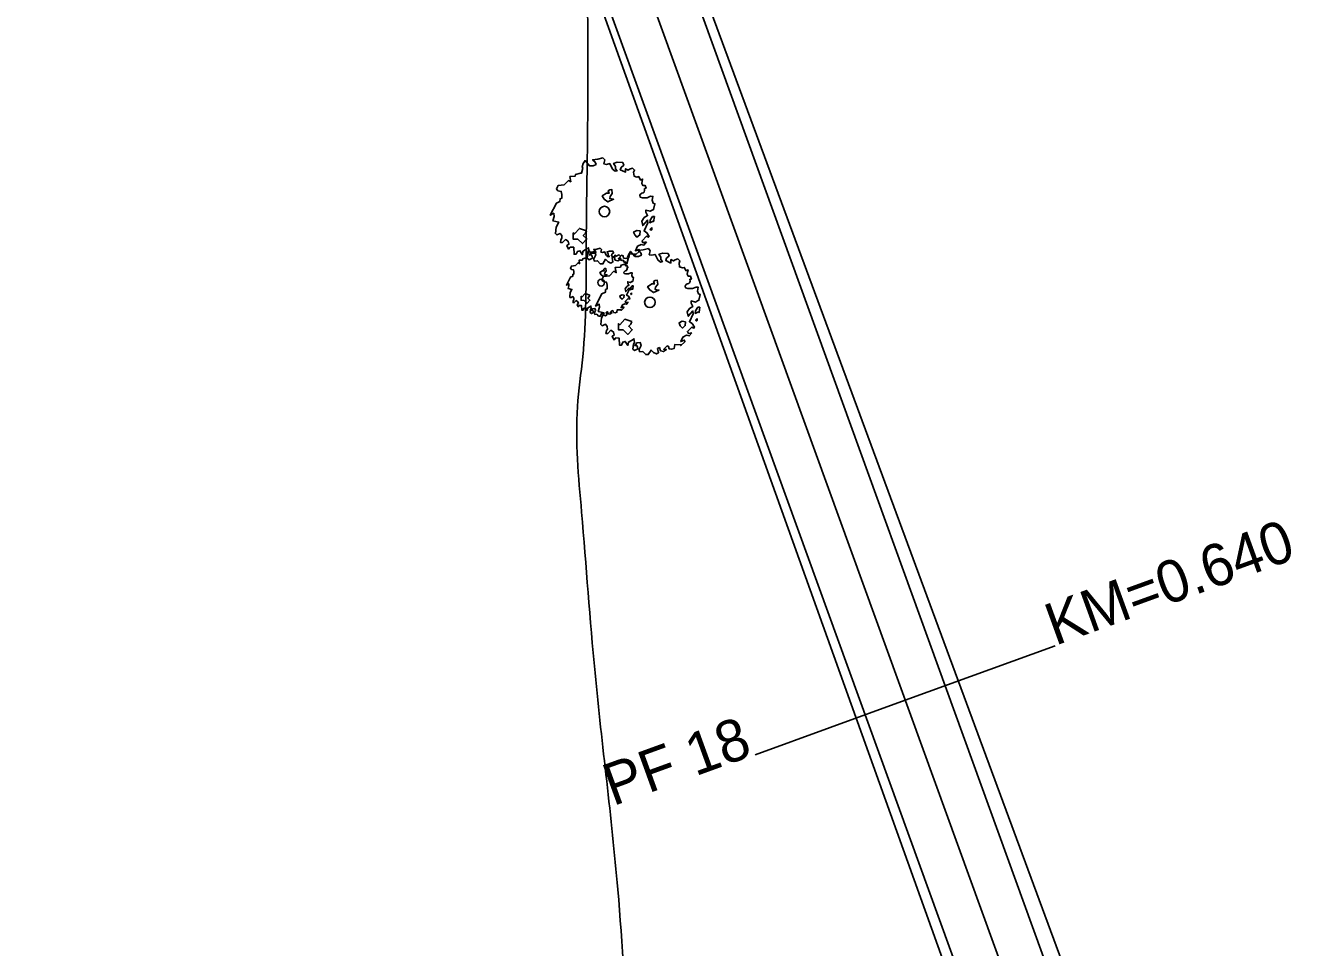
# Model space of a CAD drawing. Extents: x -475575 to -473225, y -1116053 to -1114104.
# Drawn here: x -474299.4 to -474238.8, y -1114903.1 to -1114859.8 of the extents above; entities that cross this region are included whole.
import ezdxf

# ---------------------------------------------------------------- set-up
doc = ezdxf.new("R2010")
doc.units = 0
for name, color, linetype in [('CESTN___P____KOP_N__VRH__Construction_', 7, 'Continuous'), ('IP', 7, 'Continuous'), ('POLYGONY_SITUACE_PF', 7, 'Continuous'), ('POLYGONY_SITUACE_PF_POPISY', 7, 'Continuous'), ('POLYGONY_SITUACE_PO', 7, 'Continuous'), ('Vrstevnice_vedlejsi', 7, 'Continuous')]:
    doc.layers.add(name, color=color, linetype=linetype)

msp = doc.modelspace()

# ---------------------------------------------------------------- linework, layer by layer
at = {"layer": 'CESTN___P____KOP_N__VRH__Construction_'}
for p, q in [((-474274.588, -1114840.004), (-474244.59, -1114922.733)), ((-474243.773, -1114922.437), (-474274.295, -1114839.898)), ((-474278.604, -1114841.46), (-474248.886, -1114924.291))]:
    msp.add_line(p, q, dxfattribs=at)
msp.add_lwpolyline([(-474278.348, -1114841.367), (-474248.351, -1114924.097)], dxfattribs=at)
at = {"layer": 'IP'}
for points in [[(-474270.23, -1114869.921), (-474270.344, -1114870.07), (-474270.473, -1114870.036), (-474270.649, -1114870.127), (-474270.745, -1114870.336), (-474270.574, -1114870.27), (-474270.55, -1114870.348), (-474270.744, -1114870.528), (-474270.732, -1114870.493), (-474271.028, -1114870.479), (-474271.049, -1114870.66), (-474271.178, -1114870.7), (-474271.296, -1114870.677), (-474271.321, -1114870.573), (-474271.391, -1114870.544), (-474271.544, -1114870.695), (-474271.42, -1114870.716), (-474271.563, -1114870.809), (-474271.697, -1114870.772), (-474271.747, -1114870.619), (-474271.841, -1114870.666), (-474271.799, -1114870.859), (-474271.893, -1114870.914), (-474272.029, -1114870.855), (-474272.142, -1114870.737), (-474272.271, -1114870.95), (-474272.393, -1114870.946), (-474272.523, -1114870.803), (-474272.678, -1114870.818), (-474272.702, -1114870.71), (-474272.61, -1114870.52), (-474272.659, -1114870.375), (-474272.818, -1114870.4), (-474272.902, -1114870.536), (-474272.818, -1114870.525), (-474272.781, -1114870.593), (-474272.762, -1114870.683), (-474272.915, -1114870.756), (-474273.004, -1114870.691), (-474272.974, -1114870.466), (-474272.924, -1114870.388), (-474272.951, -1114870.196), (-474272.959, -1114870.217), (-474273.207, -1114870.357), (-474273.229, -1114870.521), (-474273.351, -1114870.332), (-474273.472, -1114870.37), (-474273.528, -1114870.503), (-474273.626, -1114870.5), (-474273.643, -1114870.174), (-474273.802, -1114870.168), (-474273.88, -1114870.258), (-474273.973, -1114870.095), (-474273.872, -1114870.027), (-474273.904, -1114869.89), (-474274.028, -1114869.808), (-474274.175, -1114869.951), (-474274.263, -1114869.952), (-474274.242, -1114869.817), (-474274.196, -1114869.747), (-474274.202, -1114869.625), (-474274.285, -1114869.518), (-474274.443, -1114869.595), (-474274.504, -1114869.53), (-474274.471, -1114869.22), (-474274.349, -1114868.99), (-474274.619, -1114868.931), (-474274.564, -1114868.723), (-474274.581, -1114868.576), (-474274.749, -1114868.669), (-474274.45, -1114868.092), (-474274.288, -1114868.023), (-474274.282, -1114867.894), (-474274.207, -1114867.866), (-474274.203, -1114867.685), (-474274.23, -1114867.548), (-474274.387, -1114867.519), (-474274.457, -1114867.432), (-474274.377, -1114867.276), (-474274.093, -1114867.244), (-474273.891, -1114867.036), (-474273.78, -1114867.096), (-474273.824, -1114866.852), (-474273.579, -1114866.836), (-474273.552, -1114866.747), (-474273.328, -1114866.684), (-474273.275, -1114866.684), (-474273.212, -1114866.454), (-474273.251, -1114866.387), (-474273.192, -1114866.229), (-474273.112, -1114866.103), (-474272.902, -1114866.339), (-474272.735, -1114866.345), (-474272.592, -1114866.277), (-474272.627, -1114866.169), (-474272.755, -1114866.062), (-474272.516, -1114866.031), (-474272.27, -1114865.972), (-474272.183, -1114866.068), (-474272.224, -1114866.257), (-474272.1, -1114866.276), (-474271.949, -1114866.244), (-474271.816, -1114866.502), (-474271.702, -1114866.6), (-474271.607, -1114866.582), (-474271.684, -1114866.485), (-474271.684, -1114866.37), (-474271.769, -1114866.235), (-474271.594, -1114866.181), (-474271.341, -1114866.196), (-474271.293, -1114866.316), (-474271.414, -1114866.419), (-474271.454, -1114866.528), (-474271.243, -1114866.63), (-474271.208, -1114866.64), (-474271.205, -1114866.486), (-474271.087, -1114866.544), (-474271.014, -1114866.499), (-474270.884, -1114866.456), (-474270.782, -1114866.546), (-474270.826, -1114866.649), (-474270.809, -1114866.828), (-474270.67, -1114866.873), (-474270.585, -1114866.854), (-474270.497, -1114867.013), (-474270.403, -1114866.972), (-474270.446, -1114867.177), (-474270.395, -1114867.268), (-474270.29, -1114867.264), (-474270.245, -1114867.399), (-474270.315, -1114867.412), (-474270.309, -1114867.494), (-474270.335, -1114867.582), (-474270.373, -1114867.616), (-474270.44, -1114867.631), (-474270.5, -1114867.673), (-474270.541, -1114867.727), (-474270.517, -1114867.811), (-474270.418, -1114867.847), (-474270.197, -1114867.848), (-474270.027, -1114867.774), (-474269.923, -1114867.783), (-474269.953, -1114867.965), (-474269.909, -1114868.095), (-474269.83, -1114868.127), (-474269.892, -1114868.399), (-474269.96, -1114868.421), (-474270.055, -1114868.483), (-474270.252, -1114868.428), (-474270.26, -1114868.527), (-474270.172, -1114868.683), (-474270.33, -1114868.78), (-474270.44, -1114868.946), (-474270.397, -1114869.149), (-474270.174, -1114868.894), (-474270.162, -1114869.03), (-474270.339, -1114869.407), (-474270.204, -1114869.489), (-474270.104, -1114869.658), (-474270.125, -1114869.703), (-474270.228, -1114869.655), (-474270.432, -1114869.863), (-474270.388, -1114869.959)], [(-474271.959, -1114867.63), (-474272.102, -1114867.63), (-474272.304, -1114867.758), (-474272.207, -1114867.91), (-474272.032, -1114868.037), (-474271.772, -1114867.915), (-474271.948, -1114867.884), (-474271.93, -1114867.782), (-474271.86, -1114867.686), (-474271.83, -1114867.644), (-474271.853, -1114867.456), (-474271.947, -1114867.468), (-474272.023, -1114867.518), (-474271.993, -1114867.591)], [(-474269.939, -1114868.723), (-474270.052, -1114868.901), (-474270.066, -1114869.016), (-474269.912, -1114868.942), (-474269.888, -1114868.974), (-474269.853, -1114868.726)], [(-474273.043, -1114869.398), (-474273.371, -1114869.284), (-474273.612, -1114869.545), (-474273.665, -1114869.496), (-474273.672, -1114869.786), (-474273.452, -1114869.791), (-474273.23, -1114870), (-474273.022, -1114869.778), (-474273.191, -1114869.619), (-474273.093, -1114869.515)], [(-474270.519, -1114869.405), (-474270.676, -1114869.378), (-474270.826, -1114869.455), (-474270.774, -1114869.594), (-474270.67, -1114869.703), (-474270.533, -1114869.59)], [(-474269.973, -1114869.248), (-474270.051, -1114869.324), (-474270.014, -1114869.372), (-474269.979, -1114869.348)], [(-474271.088, -1114872.749), (-474271.161, -1114872.845), (-474271.244, -1114872.823), (-474271.356, -1114872.881), (-474271.418, -1114873.016), (-474271.308, -1114872.973), (-474271.293, -1114873.023), (-474271.417, -1114873.138), (-474271.41, -1114873.116), (-474271.599, -1114873.107), (-474271.613, -1114873.224), (-474271.695, -1114873.249), (-474271.771, -1114873.234), (-474271.787, -1114873.167), (-474271.832, -1114873.149), (-474271.93, -1114873.246), (-474271.851, -1114873.259), (-474271.942, -1114873.319), (-474272.028, -1114873.295), (-474272.061, -1114873.197), (-474272.121, -1114873.227), (-474272.094, -1114873.351), (-474272.154, -1114873.386), (-474272.241, -1114873.348), (-474272.314, -1114873.273), (-474272.397, -1114873.409), (-474272.475, -1114873.406), (-474272.558, -1114873.315), (-474272.657, -1114873.325), (-474272.673, -1114873.255), (-474272.614, -1114873.133), (-474272.645, -1114873.04), (-474272.747, -1114873.057), (-474272.801, -1114873.144), (-474272.747, -1114873.137), (-474272.723, -1114873.18), (-474272.712, -1114873.238), (-474272.81, -1114873.285), (-474272.867, -1114873.243), (-474272.847, -1114873.098), (-474272.815, -1114873.049), (-474272.832, -1114872.926), (-474272.838, -1114872.939), (-474272.997, -1114873.029), (-474273.011, -1114873.134), (-474273.089, -1114873.013), (-474273.167, -1114873.037), (-474273.203, -1114873.123), (-474273.266, -1114873.121), (-474273.276, -1114872.912), (-474273.379, -1114872.907), (-474273.428, -1114872.965), (-474273.488, -1114872.861), (-474273.424, -1114872.817), (-474273.444, -1114872.729), (-474273.523, -1114872.677), (-474273.618, -1114872.768), (-474273.674, -1114872.769), (-474273.661, -1114872.682), (-474273.631, -1114872.637), (-474273.635, -1114872.56), (-474273.688, -1114872.491), (-474273.79, -1114872.54), (-474273.829, -1114872.498), (-474273.807, -1114872.299), (-474273.729, -1114872.152), (-474273.903, -1114872.114), (-474273.867, -1114871.981), (-474273.878, -1114871.887), (-474273.986, -1114871.946), (-474273.794, -1114871.576), (-474273.69, -1114871.532), (-474273.686, -1114871.449), (-474273.638, -1114871.431), (-474273.636, -1114871.315), (-474273.653, -1114871.227), (-474273.754, -1114871.209), (-474273.798, -1114871.153), (-474273.747, -1114871.053), (-474273.565, -1114871.033), (-474273.436, -1114870.899), (-474273.364, -1114870.938), (-474273.393, -1114870.781), (-474273.236, -1114870.77), (-474273.218, -1114870.713), (-474273.074, -1114870.673), (-474273.04, -1114870.673), (-474273, -1114870.525), (-474273.025, -1114870.483), (-474272.987, -1114870.381), (-474272.936, -1114870.3), (-474272.801, -1114870.452), (-474272.694, -1114870.456), (-474272.603, -1114870.412), (-474272.625, -1114870.343), (-474272.707, -1114870.274), (-474272.554, -1114870.254), (-474272.396, -1114870.216), (-474272.34, -1114870.278), (-474272.366, -1114870.4), (-474272.287, -1114870.412), (-474272.19, -1114870.391), (-474272.105, -1114870.556), (-474272.031, -1114870.619), (-474271.971, -1114870.608), (-474272.02, -1114870.545), (-474272.02, -1114870.472), (-474272.074, -1114870.385), (-474271.962, -1114870.351), (-474271.8, -1114870.36), (-474271.769, -1114870.437), (-474271.847, -1114870.503), (-474271.872, -1114870.573), (-474271.737, -1114870.639), (-474271.714, -1114870.645), (-474271.713, -1114870.546), (-474271.637, -1114870.583), (-474271.59, -1114870.555), (-474271.507, -1114870.527), (-474271.441, -1114870.585), (-474271.47, -1114870.651), (-474271.459, -1114870.765), (-474271.37, -1114870.794), (-474271.315, -1114870.782), (-474271.259, -1114870.884), (-474271.199, -1114870.858), (-474271.226, -1114870.989), (-474271.193, -1114871.048), (-474271.126, -1114871.045), (-474271.097, -1114871.132), (-474271.142, -1114871.14), (-474271.138, -1114871.193), (-474271.155, -1114871.249), (-474271.18, -1114871.271), (-474271.222, -1114871.28), (-474271.261, -1114871.308), (-474271.287, -1114871.342), (-474271.272, -1114871.396), (-474271.208, -1114871.419), (-474271.066, -1114871.42), (-474270.957, -1114871.372), (-474270.89, -1114871.378), (-474270.91, -1114871.495), (-474270.881, -1114871.578), (-474270.831, -1114871.598), (-474270.871, -1114871.773), (-474270.914, -1114871.787), (-474270.975, -1114871.827), (-474271.102, -1114871.792), (-474271.107, -1114871.855), (-474271.051, -1114871.955), (-474271.152, -1114872.018), (-474271.222, -1114872.124), (-474271.195, -1114872.254), (-474271.052, -1114872.091), (-474271.044, -1114872.178), (-474271.158, -1114872.419), (-474271.071, -1114872.472), (-474271.007, -1114872.58), (-474271.02, -1114872.609), (-474271.086, -1114872.578), (-474271.217, -1114872.712), (-474271.189, -1114872.773)], [(-474268.097, -1114874.186), (-474268.211, -1114874.335), (-474268.34, -1114874.301), (-474268.516, -1114874.392), (-474268.611, -1114874.601), (-474268.44, -1114874.535), (-474268.417, -1114874.613), (-474268.61, -1114874.792), (-474268.599, -1114874.757), (-474268.894, -1114874.743), (-474268.915, -1114874.925), (-474269.044, -1114874.964), (-474269.162, -1114874.942), (-474269.187, -1114874.837), (-474269.258, -1114874.808), (-474269.411, -1114874.959), (-474269.287, -1114874.981), (-474269.429, -1114875.074), (-474269.563, -1114875.037), (-474269.614, -1114874.884), (-474269.708, -1114874.931), (-474269.666, -1114875.124), (-474269.759, -1114875.178), (-474269.895, -1114875.12), (-474270.009, -1114875.002), (-474270.137, -1114875.215), (-474270.26, -1114875.21), (-474270.389, -1114875.068), (-474270.544, -1114875.083), (-474270.568, -1114874.975), (-474270.477, -1114874.784), (-474270.525, -1114874.64), (-474270.684, -1114874.665), (-474270.768, -1114874.801), (-474270.684, -1114874.79), (-474270.647, -1114874.858), (-474270.629, -1114874.948), (-474270.782, -1114875.02), (-474270.871, -1114874.955), (-474270.84, -1114874.73), (-474270.79, -1114874.652), (-474270.817, -1114874.461), (-474270.825, -1114874.481), (-474271.074, -1114874.622), (-474271.095, -1114874.785), (-474271.218, -1114874.597), (-474271.339, -1114874.634), (-474271.395, -1114874.768), (-474271.492, -1114874.765), (-474271.509, -1114874.439), (-474271.668, -1114874.432), (-474271.746, -1114874.523), (-474271.839, -1114874.36), (-474271.739, -1114874.291), (-474271.77, -1114874.154), (-474271.894, -1114874.073), (-474272.042, -1114874.215), (-474272.129, -1114874.216), (-474272.109, -1114874.081), (-474272.062, -1114874.011), (-474272.068, -1114873.89), (-474272.151, -1114873.783), (-474272.31, -1114873.86), (-474272.37, -1114873.794), (-474272.337, -1114873.484), (-474272.215, -1114873.255), (-474272.486, -1114873.195), (-474272.431, -1114872.987), (-474272.447, -1114872.841), (-474272.616, -1114872.934), (-474272.316, -1114872.357), (-474272.154, -1114872.288), (-474272.148, -1114872.158), (-474272.073, -1114872.131), (-474272.07, -1114871.95), (-474272.097, -1114871.813), (-474272.253, -1114871.784), (-474272.323, -1114871.697), (-474272.243, -1114871.541), (-474271.96, -1114871.509), (-474271.758, -1114871.301), (-474271.646, -1114871.361), (-474271.691, -1114871.117), (-474271.446, -1114871.1), (-474271.419, -1114871.012), (-474271.194, -1114870.948), (-474271.141, -1114870.949), (-474271.079, -1114870.718), (-474271.117, -1114870.652), (-474271.058, -1114870.494), (-474270.978, -1114870.368), (-474270.768, -1114870.604), (-474270.601, -1114870.61), (-474270.459, -1114870.542), (-474270.494, -1114870.433), (-474270.621, -1114870.326), (-474270.383, -1114870.296), (-474270.136, -1114870.236), (-474270.049, -1114870.333), (-474270.09, -1114870.522), (-474269.966, -1114870.541), (-474269.815, -1114870.509), (-474269.682, -1114870.767), (-474269.568, -1114870.865), (-474269.474, -1114870.847), (-474269.551, -1114870.749), (-474269.551, -1114870.635), (-474269.635, -1114870.5), (-474269.461, -1114870.446), (-474269.208, -1114870.461), (-474269.159, -1114870.581), (-474269.28, -1114870.684), (-474269.32, -1114870.793), (-474269.109, -1114870.895), (-474269.074, -1114870.905), (-474269.072, -1114870.75), (-474268.954, -1114870.809), (-474268.881, -1114870.764), (-474268.75, -1114870.721), (-474268.648, -1114870.811), (-474268.692, -1114870.914), (-474268.675, -1114871.092), (-474268.537, -1114871.137), (-474268.451, -1114871.119), (-474268.363, -1114871.277), (-474268.27, -1114871.236), (-474268.313, -1114871.441), (-474268.261, -1114871.533), (-474268.157, -1114871.528), (-474268.112, -1114871.663), (-474268.182, -1114871.677), (-474268.175, -1114871.759), (-474268.201, -1114871.846), (-474268.24, -1114871.881), (-474268.306, -1114871.895), (-474268.366, -1114871.938), (-474268.408, -1114871.992), (-474268.384, -1114872.075), (-474268.284, -1114872.112), (-474268.064, -1114872.112), (-474267.893, -1114872.039), (-474267.789, -1114872.048), (-474267.82, -1114872.23), (-474267.775, -1114872.36), (-474267.697, -1114872.391), (-474267.758, -1114872.664), (-474267.826, -1114872.686), (-474267.921, -1114872.748), (-474268.119, -1114872.693), (-474268.126, -1114872.791), (-474268.039, -1114872.947), (-474268.197, -1114873.045), (-474268.307, -1114873.211), (-474268.264, -1114873.413), (-474268.041, -1114873.159), (-474268.029, -1114873.294), (-474268.206, -1114873.672), (-474268.071, -1114873.754), (-474267.971, -1114873.922), (-474267.991, -1114873.968), (-474268.094, -1114873.919), (-474268.298, -1114874.127), (-474268.255, -1114874.223)], [(-474272.197, -1114871.28), (-474272.288, -1114871.28), (-474272.418, -1114871.362), (-474272.356, -1114871.459), (-474272.243, -1114871.541), (-474272.077, -1114871.463), (-474272.189, -1114871.443), (-474272.178, -1114871.377), (-474272.133, -1114871.316), (-474272.114, -1114871.289), (-474272.128, -1114871.169), (-474272.189, -1114871.176), (-474272.237, -1114871.208), (-474272.218, -1114871.255)], [(-474270.901, -1114871.981), (-474270.973, -1114872.095), (-474270.983, -1114872.169), (-474270.884, -1114872.121), (-474270.868, -1114872.142), (-474270.846, -1114871.983)], [(-474269.826, -1114871.894), (-474269.968, -1114871.894), (-474270.17, -1114872.023), (-474270.073, -1114872.174), (-474269.899, -1114872.302), (-474269.639, -1114872.18), (-474269.815, -1114872.149), (-474269.797, -1114872.047), (-474269.727, -1114871.95), (-474269.696, -1114871.909), (-474269.719, -1114871.721), (-474269.813, -1114871.732), (-474269.889, -1114871.783), (-474269.859, -1114871.855)], [(-474272.892, -1114872.414), (-474273.102, -1114872.341), (-474273.257, -1114872.508), (-474273.291, -1114872.476), (-474273.295, -1114872.662), (-474273.154, -1114872.666), (-474273.012, -1114872.8), (-474272.878, -1114872.657), (-474272.987, -1114872.555), (-474272.924, -1114872.489)], [(-474271.273, -1114872.418), (-474271.373, -1114872.401), (-474271.47, -1114872.451), (-474271.437, -1114872.539), (-474271.37, -1114872.61), (-474271.282, -1114872.537)], [(-474270.922, -1114872.318), (-474270.973, -1114872.366), (-474270.949, -1114872.397), (-474270.927, -1114872.382)], [(-474267.806, -1114872.988), (-474267.918, -1114873.165), (-474267.933, -1114873.28), (-474267.779, -1114873.206), (-474267.755, -1114873.238), (-474267.719, -1114872.991)], [(-474270.91, -1114873.662), (-474271.237, -1114873.549), (-474271.478, -1114873.81), (-474271.532, -1114873.76), (-474271.538, -1114874.05), (-474271.319, -1114874.055), (-474271.097, -1114874.264), (-474270.888, -1114874.043), (-474271.057, -1114873.883), (-474270.959, -1114873.779)], [(-474268.386, -1114873.669), (-474268.542, -1114873.643), (-474268.692, -1114873.72), (-474268.641, -1114873.858), (-474268.537, -1114873.968), (-474268.4, -1114873.854)], [(-474267.839, -1114873.513), (-474267.918, -1114873.589), (-474267.88, -1114873.637), (-474267.845, -1114873.613)]]:
    msp.add_lwpolyline(points, close=True, dxfattribs=at)
for centre, radius in [((-474272.199, -1114868.492), 0.247), ((-474272.35, -1114871.833), 0.158), ((-474270.065, -1114872.757), 0.247)]:
    msp.add_circle(centre, radius, dxfattribs=at)
at = {"layer": 'POLYGONY_SITUACE_PF'}
msp.add_lwpolyline([(-474265.111, -1114894.008), (-474258.06, -1114891.451), (-474251.01, -1114888.895)], dxfattribs=at)
at = {"layer": 'POLYGONY_SITUACE_PO'}
msp.add_lwpolyline([(-474033.93, -1115484.017), (-474028.81, -1115469.55), (-474027.706, -1115465.586), (-474027.155, -1115461.509), (-474027.167, -1115457.394), (-474027.702, -1115449.947), (-474028.133, -1115446.706), (-474028.952, -1115443.542), (-474030.148, -1115440.499), (-474155.776, -1115170.193), (-474159.336, -1115162.232), (-474162.663, -1115154.172), (-474165.754, -1115146.018), (-474287.504, -1114810.25), (-474291.915, -1114795.876)], dxfattribs=at)
at = {"layer": 'Vrstevnice_vedlejsi'}
for points in [[(-474198.341, -1114669.49), (-474196.681, -1114672.256), (-474195.18, -1114674.653), (-474193.836, -1114676.681), (-474192.651, -1114678.341), (-474192.443, -1114683.526), (-474193.214, -1114692.237), (-474194.962, -1114704.473), (-474196.31, -1114712.997), (-474197.258, -1114717.807), (-474197.807, -1114718.903), (-474198.355, -1114720.033), (-474198.903, -1114721.196), (-474199.452, -1114722.393), (-474202.29, -1114724.764), (-474207.417, -1114728.309), (-474214.834, -1114733.029), (-474221.352, -1114738.648), (-474226.971, -1114745.166), (-474231.691, -1114752.583), (-474235.037, -1114757.727), (-474237.009, -1114760.598), (-474237.607, -1114761.196), (-474238.205, -1114762.022), (-474238.804, -1114763.076), (-474239.402, -1114764.358), (-474242.028, -1114769.031), (-474246.681, -1114777.093), (-474253.362, -1114788.547), (-474258.559, -1114799.152), (-474262.27, -1114808.908), (-474264.497, -1114817.816), (-474266.676, -1114825.23), (-474268.807, -1114831.15), (-474270.889, -1114835.575), (-474272.278, -1114842.188), (-474272.972, -1114850.991), (-474272.972, -1114861.981), (-474273.054, -1114870.089), (-474273.218, -1114875.314), (-474273.465, -1114877.657), (-474273.273, -1114882.608), (-474272.641, -1114890.167), (-474271.571, -1114900.334), (-474271.061, -1114908.167), (-474271.11, -1114913.667), (-474271.719, -1114916.834), (-474271.646, -1114922.058), (-474270.891, -1114929.339), (-474269.454, -1114938.678), (-474268.091, -1114946.236), (-474266.802, -1114952.012), (-474265.586, -1114956.006), (-474264.292, -1114960.893), (-474262.92, -1114966.673), (-474261.469, -1114973.346), (-474259.897, -1114980.014), (-474258.202, -1114986.679), (-474256.386, -1114993.34), (-474254.916, -1115000.31), (-474253.793, -1115007.591), (-474253.017, -1115015.182), (-474252.121, -1115021.507), (-474251.104, -1115026.568), (-474249.968, -1115030.364), (-474249.22, -1115033.873), (-474248.86, -1115037.095), (-474248.889, -1115040.031), (-474248.926, -1115042.279), (-474248.97, -1115043.838), (-474249.022, -1115044.709), (-474249.185, -1115045.346), (-474249.46, -1115045.75), (-474249.845, -1115045.92), (-474250.053, -1115046.628), (-474250.085, -1115047.873), (-474249.939, -1115049.656), (-474250.24, -1115054.341), (-474250.987, -1115061.928), (-474252.18, -1115072.418), (-474252.552, -1115080.569), (-474252.103, -1115086.383), (-474250.833, -1115089.859), (-474248.888, -1115093.001), (-474246.267, -1115095.808), (-474242.971, -1115098.281), (-474237.53, -1115101.018), (-474229.942, -1115104.018), (-474220.207, -1115107.282), (-474212.554, -1115110.016), (-474206.982, -1115112.221), (-474203.491, -1115113.895), (-474200.507, -1115114.848), (-474198.031, -1115115.078), (-474196.062, -1115114.586), (-474193.634, -1115114.914), (-474190.746, -1115116.062)], [(-474227.218, -1115164.851), (-474226.448, -1115162.426), (-474227.525, -1115159.571), (-474230.451, -1115156.287), (-474235.226, -1115152.573), (-474240.399, -1115148.881), (-474245.971, -1115145.211), (-474251.942, -1115141.562), (-474256.818, -1115137.139), (-474260.6, -1115131.942), (-474263.287, -1115125.971), (-474265.918, -1115121.36), (-474268.492, -1115118.11), (-474271.011, -1115116.221), (-474273.409, -1115112.993), (-474275.686, -1115108.429), (-474277.843, -1115102.526), (-474279.974, -1115096.744), (-474282.078, -1115091.082), (-474284.156, -1115085.541), (-474285.812, -1115080.883), (-474287.047, -1115077.109), (-474287.86, -1115074.218), (-474288.244, -1115068.81), (-474288.198, -1115060.885), (-474287.724, -1115050.442), (-474287.488, -1115042.595), (-474287.491, -1115037.342), (-474287.732, -1115034.684), (-474288.91, -1115029.354), (-474291.024, -1115021.351), (-474294.074, -1115010.675), (-474297.009, -1115000.754), (-474299.828, -1114991.588), (-474302.532, -1114983.176), (-474304.676, -1114975.928), (-474306.261, -1114969.843), (-474307.286, -1114964.921), (-474309.265, -1114957.199), (-474312.198, -1114946.677), (-474316.084, -1114933.354), (-474318.675, -1114924.468), (-474319.971, -1114920.02), (-474319.973, -1114920.01), (-474319.977, -1114919.992), (-474319.984, -1114919.965), (-474319.992, -1114919.931), (-474321.301, -1114916.779), (-474323.911, -1114910.509), (-474327.823, -1114901.121), (-474333.571, -1114893.897), (-474341.156, -1114888.835), (-474350.578, -1114885.936), (-474361.246, -1114883.666), (-474373.16, -1114882.025), (-474386.32, -1114881.012), (-474395.152, -1114880.336), (-474399.654, -1114879.994), (-474399.827, -1114879.989), (-474403.877, -1114879.477), (-474411.805, -1114878.46), (-474423.609, -1114876.937), (-474431.988, -1114875.62), (-474436.942, -1114874.51), (-474438.471, -1114873.607), (-474443.932, -1114869.371), (-474453.324, -1114861.802), (-474466.647, -1114850.901), (-474475.533, -1114843.63), (-474479.981, -1114839.989), (-474479.99, -1114839.978), (-474480.008, -1114839.975), (-474480.035, -1114839.978), (-474480.069, -1114839.989), (-474480.092, -1114840.008), (-474480.104, -1114840.035), (-474480.104, -1114840.069), (-474483.152, -1114844.525), (-474489.247, -1114853.403), (-474498.39, -1114866.701), (-474505.505, -1114879.646), (-474510.592, -1114892.237), (-474513.651, -1114904.473), (-474515.798, -1114912.997), (-474517.033, -1114917.807), (-474517.355, -1114918.903), (-474517.71, -1114919.879), (-474518.097, -1114920.733), (-474518.517, -1114921.467), (-474518.841, -1114922.054), (-474519.069, -1114922.494), (-474519.202, -1114922.788), (-474519.513, -1114923.611), (-474520.002, -1114924.961), (-474520.669, -1114926.839), (-474521.912, -1114930.34), (-474523.73, -1114935.464)]]:
    msp.add_spline(points, degree=3, dxfattribs=at)

# ---------------------------------------------------------------- texts
at = {"layer": 'POLYGONY_SITUACE_PF_POPISY'}
for s, p in [('KM=0.640', (-474251.021, -1114888.899)), ('PF 18', (-474271.8, -1114896.434))]:
    msp.add_text(s, height=1.9765, rotation=19.93072, dxfattribs=at).set_placement(p)

doc.saveas('drawing.dxf')
